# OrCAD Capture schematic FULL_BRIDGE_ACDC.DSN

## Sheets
1 PAGE2: size A
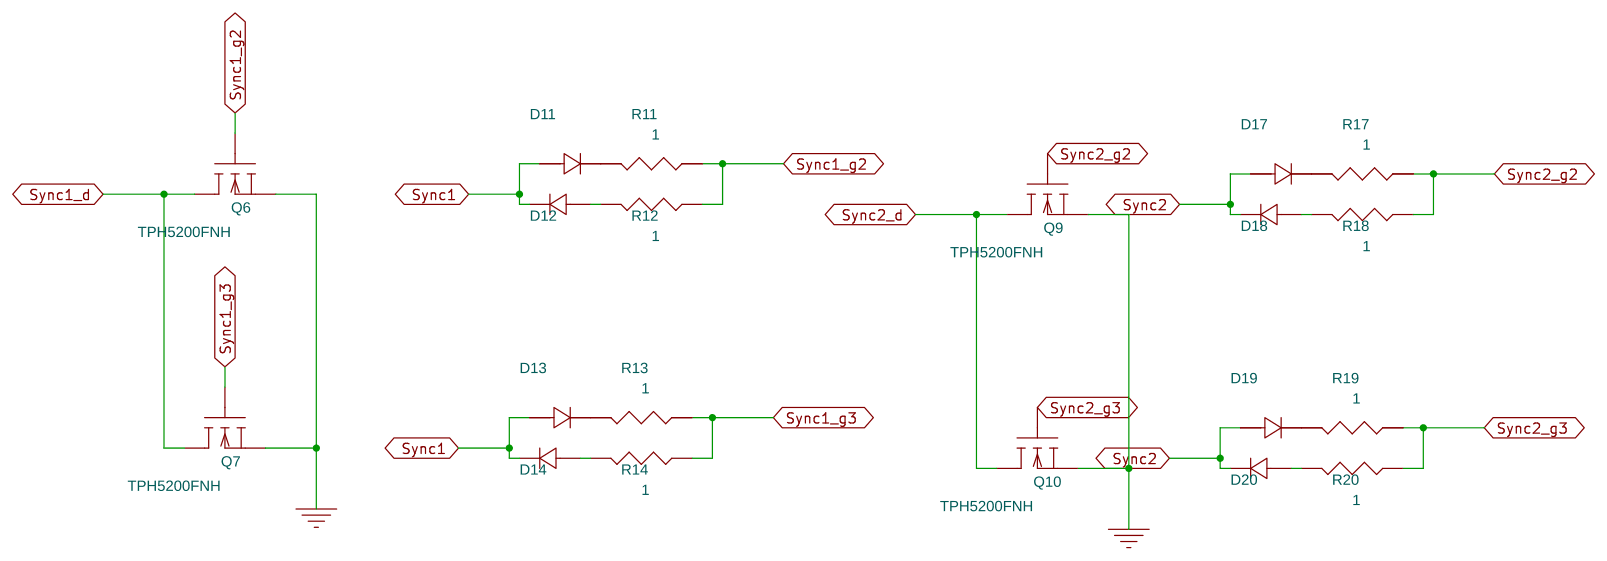
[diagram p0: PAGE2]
2 PAGE1: size A
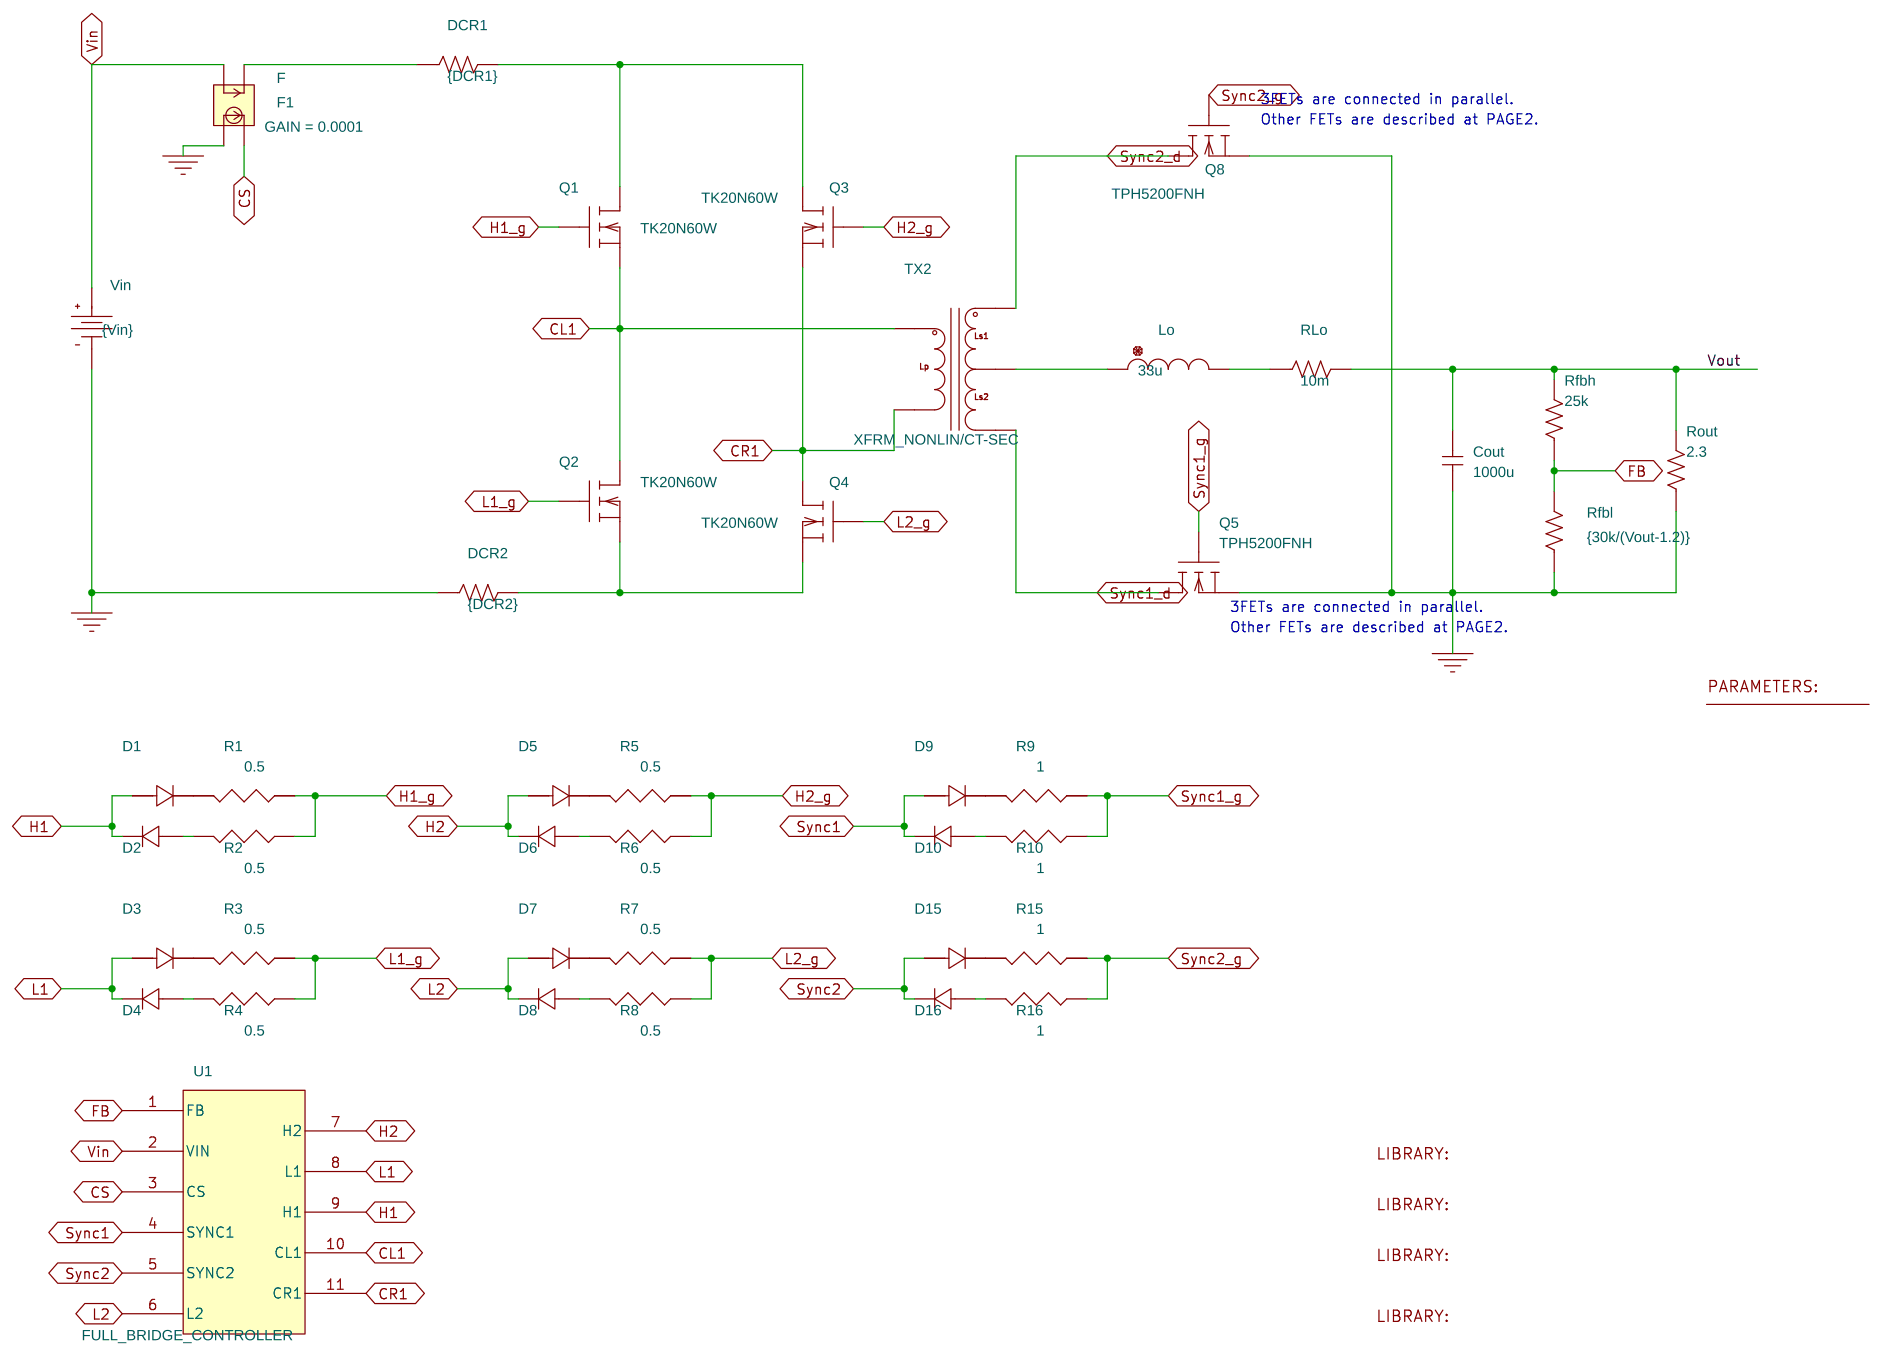
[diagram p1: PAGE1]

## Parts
sheet PAGE1
1  PARAM
Cout  1000u  [cap196]
D1  Diode_nom
D2  Diode_nom
D3  Diode_nom
D4  Diode_nom
D5  Diode_nom
D6  Diode_nom
D7  Diode_nom
D8  Diode_nom
D9  Diode_nom
D10  Diode_nom
D15  Diode_nom
D16  Diode_nom
DCR1  {DCR1}  [AXRC05]
DCR2  {DCR2}  [AXRC05]
F1  F
LIB4  LIB
LIB5  LIB
LIB6  LIB
LIB7  LIB
Lo  33u  [DISC350x175LS200x100034]
Q1  TK20N60W
Q2  TK20N60W
Q3  TK20N60W
Q4  TK20N60W
Q5  TPH5200FNH
Q8  TPH5200FNH
R1  0.5  [AXRC05]
R2  0.5  [AXRC05]
R3  0.5  [AXRC05]
R4  0.5  [AXRC05]
R5  0.5  [AXRC05]
R6  0.5  [AXRC05]
R7  0.5  [AXRC05]
R8  0.5  [AXRC05]
R9  1  [AXRC05]
R10  1  [AXRC05]
R15  1  [AXRC05]
R16  1  [AXRC05]
Rfbh  25k  [AXRC05]
Rfbl  {30k/(Vout-1.2)}  [AXRC05]
RLo  10m  [AXRC05]
Rout  2.3  [AXRC05]
TX2  XFRM_NONLIN/CT-SEC
U1  FULL_BRIDGE_CONTROLLER
Vin  VDC
sheet PAGE2
D11  Diode_nom
D12  Diode_nom
D13  Diode_nom
D14  Diode_nom
D17  Diode_nom
D18  Diode_nom
D19  Diode_nom
D20  Diode_nom
Q6  TPH5200FNH
Q7  TPH5200FNH
Q9  TPH5200FNH
Q10  TPH5200FNH
R11  1  [AXRC05]
R12  1  [AXRC05]
R13  1  [AXRC05]
R14  1  [AXRC05]
R17  1  [AXRC05]
R18  1  [AXRC05]
R19  1  [AXRC05]
R20  1  [AXRC05]

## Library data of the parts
1 = PARAM: DCR1: 5m; DCR2: 5m; Fc: 200k; Rdrv_off_p: 1.5; Rdrv_off_s: 0.5; Rdrv_on_p: 5.8; Rdrv_on_s: 5; Tdl: 300n; Tdr: 300n; Vdrv_H_p: 12; Vdrv_H_s: 12; Vin: 380; Vout: 48
Cout = C
D1-D20 = Diode_nom
DCR1 DCR2 Rfbh Rfbl RLo Rout = R_v2
F1 = F: GAIN: 0.0001
LIB4 = LIB: FILENAME: ../../../Lib/TPH5200FNH_PSpice_20160128.lib
LIB5 = LIB: FILENAME: ../../../Lib/TK20N60W_PSpice_20140204.lib
LIB6 = LIB: FILENAME: ../../../Lib/diode_nom.lib
LIB7 = LIB: FILENAME: ../../../Lib/Full_bridge_controller.lib
Lo = L
Q1-Q4 = TK20N60W
Q5-Q10 = TPH5200FNH
R1-R20 = R
TX2 = XFRM_NONLIN_CT-SEC: COUPLING: 1; LP_TURNS: 400; LS1_TURNS: 100; LS2_TURNS: 100; RP_VALUE: 1e-3; RS_VALUE: 1e-3
U1 = FULL_BRIDGE_CONTROLLER
Vin = VDC: DC: {Vin}

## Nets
Vin: F1.1 U1.2(VIN) Vin.0(+)
0: Cout.1 DCR2.1 F1.3 Q5.0(s) Q6.0(s) Q7.0(s) Q8.0(s) Q9.0(s) Q10.0(s) Rfbl.1 Rout.1 Vin.1(-)
CL1: Q1.0(s) Q2.2(d) TX2.0(1) U1.10(CL1)
CR1: Q3.0(s) Q4.2(d) TX2.1(3) U1.11(CR1)
CS: F1.4 U1.3(CS)
FB: Rfbh.1 Rfbl.2 U1.1(FB)
H1: D1.0(1) D2.1(2) U1.9(H1)
H1_g: Q1.1(g) R1.1 R2.1
H2: D5.0(1) D6.1(2) U1.7(H2)
H2_g: Q3.1(g) R5.1 R6.1
L1: D3.0(1) D4.1(2) U1.8(L1)
L1_g: Q2.1(g) R3.1 R4.1
L2: D7.0(1) D8.1(2) U1.6(L2)
L2_g: Q4.1(g) R7.1 R8.1
Sync1: D9.0(1) D10.1(2) D11.0(1) D12.1(2) D13.0(1) D14.1(2) U1.4(SYNC1)
Sync1_d: Q5.2(d) Q6.2(d) Q7.2(d) TX2.4(6)
Sync1_g: Q5.1(g) R9.1 R10.1
Sync1_g2: Q6.1(g) R11.1 R12.1
Sync1_g3: Q7.1(g) R13.1 R14.1
Sync2: D15.0(1) D16.1(2) D17.0(1) D18.1(2) D19.0(1) D20.1(2) U1.5(SYNC2)
Sync2_d: Q8.2(d) Q9.2(d) Q10.2(d) TX2.2(4)
Sync2_g: Q8.1(g) R15.1 R16.1
Sync2_g2: Q9.1(g) R17.1 R18.1
Sync2_g3: Q10.1(g) R19.1 R20.1
Vout: Cout.2 Rfbh.2 RLo.2 Rout.2
N2441083: DCR1.1 F1.2
N2441087: DCR1.2 Q1.2(d) Q3.2(d)
N2441369: Lo.1 TX2.3(5)
N2441377: Lo.2 RLo.1
N2441611: DCR2.2 Q2.0(s) Q4.0(s)
N2442139: D2.0(1) R2.2
N2442167: D6.0(1) R6.2
N2442195: D10.0(1) R10.2
N2442595: D4.0(1) R4.2
N2442623: D8.0(1) R8.2
N2442651: D16.0(1) R16.2
N2444041: D12.0(1) R12.2
N2444089: D18.0(1) R18.2
N2444391: D14.0(1) R14.2
N2444473: D20.0(1) R20.2
N2461113: D1.1(2) R1.2
N2461133: D3.1(2) R3.2
N2461155: D5.1(2) R5.2
N2461175: D7.1(2) R7.2
N2461195: D9.1(2) R9.2
N2461228: D11.1(2) R11.2
N2461248: D13.1(2) R13.2
N2461267: D15.1(2) R15.2
N2461298: D17.1(2) R17.2
N2461318: D19.1(2) R19.2

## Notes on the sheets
sheet 2
- 3FETs are connected in parallel.
- Other FETs are described at PAGE2.
- 3FETs are connected in parallel.
- Other FETs are described at PAGE2.
